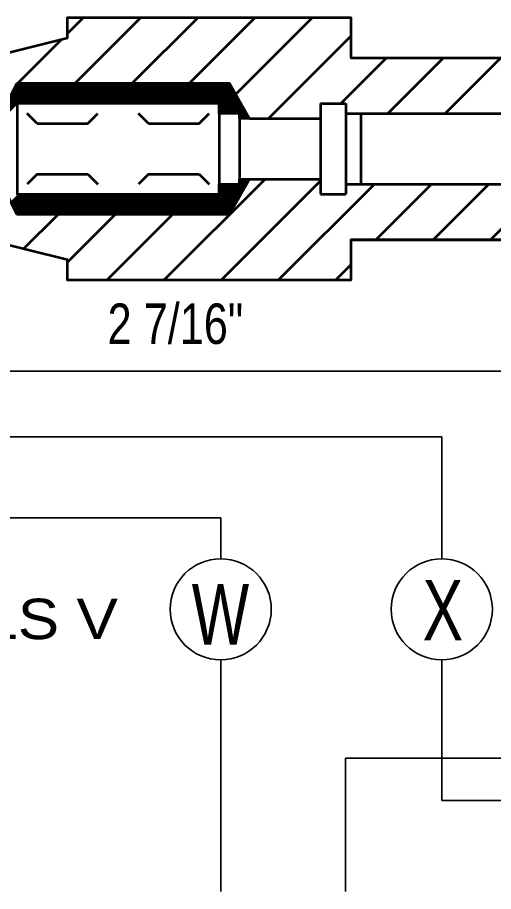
# Model space of a CAD drawing. Extents: x -1 to 679, y 0 to 440.
# Drawn here: x 318.92 to 342.46, y 108.8 to 152.05 of the extents above; entities that cross this region are included whole.
import ezdxf

# ---------------------------------------------------------------- set-up
doc = ezdxf.new("R2010")
doc.units = 0
doc.header["$LTSCALE"] = 0.8
doc.layers.add('1', color=7, linetype='Continuous', lineweight=53)

msp = doc.modelspace()

# ---------------------------------------------------------------- linework, layer by layer
at = {"layer": '1'}
for p, q in [((321.3991, 151.2609), (322.1895, 152.0513)), ((321.7679, 148.8013), (325.0179, 152.0513)), ((324.5963, 148.8013), (327.8463, 152.0513)), ((327.4248, 148.8013), (330.6748, 152.0513)), ((329.7097, 148.2577), (333.5032, 152.0513)), ((318.9395, 148.8013), (321.1197, 150.9815)), ((331.3317, 147.0513), (335.3991, 151.1188)), ((334.9101, 147.8013), (337.1601, 150.0513)), ((337.2385, 147.3013), (339.9885, 150.0513)), ((340.0669, 147.3013), (342.8169, 150.0513)), ((316.5665, 145.9263), (319.4415, 148.8013)), ((316.7079, 145.9263), (319.5829, 148.8013)), ((316.8493, 145.9263), (319.7243, 148.8013)), ((316.9907, 145.9263), (319.8657, 148.8013)), ((318.4981, 147.9994), (319.3001, 148.8013)), ((318.6395, 148.2823), (319.1587, 148.8013)), ((318.7809, 148.5651), (319.0172, 148.8013)), ((319.0072, 147.8013), (320.0072, 148.8013)), ((319.1486, 147.8013), (320.1486, 148.8013)), ((319.29, 147.8013), (320.29, 148.8013)), ((319.4314, 147.8013), (320.4314, 148.8013)), ((319.5728, 147.8013), (320.5728, 148.8013)), ((319.7142, 147.8013), (320.7142, 148.8013)), ((319.8557, 147.8013), (320.8557, 148.8013)), ((319.9971, 147.8013), (320.9971, 148.8013)), ((320.1385, 147.8013), (321.1385, 148.8013)), ((320.2799, 147.8013), (321.2799, 148.8013)), ((320.4214, 147.8013), (321.4214, 148.8013)), ((320.5628, 147.8013), (321.5628, 148.8013)), ((320.7043, 147.8013), (321.7043, 148.8013)), ((320.8457, 147.8013), (321.8457, 148.8013)), ((320.9871, 147.8013), (321.9871, 148.8013)), ((321.1285, 147.8013), (322.1285, 148.8013)), ((321.2699, 147.8013), (322.2699, 148.8013)), ((321.4113, 147.8013), (322.4113, 148.8013)), ((321.5528, 147.8013), (322.5528, 148.8013)), ((321.6942, 147.8013), (322.6942, 148.8013)), ((321.8356, 147.8013), (322.8356, 148.8013)), ((321.977, 147.8013), (322.977, 148.8013)), ((322.1184, 147.8013), (323.1184, 148.8013)), ((322.2598, 147.8013), (323.2598, 148.8013)), ((322.4013, 147.8013), (323.4013, 148.8013)), ((322.5427, 147.8013), (323.5427, 148.8013)), ((322.6841, 147.8013), (323.6841, 148.8013)), ((322.8255, 147.8013), (323.8255, 148.8013)), ((322.967, 147.8013), (323.967, 148.8013)), ((323.1084, 147.8013), (324.1084, 148.8013)), ((323.2498, 147.8013), (324.2498, 148.8013)), ((323.3913, 147.8013), (324.3913, 148.8013)), ((323.5327, 147.8013), (324.5327, 148.8013)), ((323.6741, 147.8013), (324.6741, 148.8013)), ((323.8155, 147.8013), (324.8155, 148.8013)), ((323.9569, 147.8013), (324.9569, 148.8013)), ((324.0983, 147.8013), (325.0983, 148.8013)), ((324.2398, 147.8013), (325.2398, 148.8013)), ((324.3812, 147.8013), (325.3812, 148.8013)), ((324.5226, 147.8013), (325.5226, 148.8013)), ((324.664, 147.8013), (325.664, 148.8013)), ((324.8054, 147.8013), (325.8054, 148.8013)), ((324.9468, 147.8013), (325.9468, 148.8013)), ((325.0883, 147.8013), (326.0883, 148.8013)), ((325.2297, 147.8013), (326.2297, 148.8013)), ((325.3711, 147.8013), (326.3711, 148.8013)), ((325.5126, 147.8013), (326.5126, 148.8013)), ((325.654, 147.8013), (326.654, 148.8013)), ((325.7954, 147.8013), (326.7954, 148.8013)), ((325.9368, 147.8013), (326.9368, 148.8013)), ((326.0782, 147.8013), (327.0782, 148.8013)), ((326.2197, 147.8013), (327.2197, 148.8013)), ((326.3611, 147.8013), (327.3611, 148.8013)), ((326.5025, 147.8013), (327.5025, 148.8013)), ((326.6439, 147.8013), (327.6439, 148.8013)), ((326.7853, 147.8013), (327.7853, 148.8013)), ((326.9267, 147.8013), (327.9267, 148.8013)), ((327.0682, 147.8013), (328.0682, 148.8013)), ((327.2096, 147.8013), (328.2096, 148.8013)), ((327.351, 147.8013), (328.351, 148.8013)), ((327.4924, 147.8013), (328.4924, 148.8013)), ((327.6338, 147.8013), (328.6338, 148.8013)), ((327.7752, 147.8013), (328.7752, 148.8013)), ((327.9167, 147.8013), (328.9167, 148.8013)), ((328.0582, 147.8013), (329.0582, 148.8013)), ((328.1996, 147.8013), (329.1996, 148.8013)), ((328.341, 147.8013), (329.341, 148.8013)), ((328.4824, 147.8013), (329.4294, 148.7483)), ((328.6238, 147.8013), (329.4808, 148.6583)), ((328.7652, 147.8013), (329.5322, 148.5683)), ((328.8991, 147.7937), (329.5837, 148.4783)), ((328.8991, 147.6523), (329.6351, 148.3883)), ((328.8991, 147.5109), (329.6865, 148.2983)), ((328.8991, 147.3695), (329.7379, 148.2083)), ((328.9723, 147.3013), (329.7893, 148.1183)), ((329.1137, 147.3013), (329.8408, 148.0283)), ((329.2552, 147.3013), (329.8922, 147.9383)), ((329.3966, 147.3013), (329.9437, 147.8483)), ((329.538, 147.3013), (329.9951, 147.7583)), ((329.6794, 147.3013), (330.0465, 147.6683)), ((329.8208, 147.3013), (330.0979, 147.5784)), ((329.8991, 147.2381), (330.1493, 147.4884)), ((333.8991, 147.8013), (333.8991, 143.3013)), ((333.8991, 147.8013), (335.1491, 147.8013)), ((335.1491, 147.8013), (335.1491, 143.3013)), ((319.8991, 146.8013), (319.3991, 147.3013)), ((322.3991, 146.8013), (322.8991, 147.3013)), ((325.3991, 146.8013), (324.8991, 147.3013)), ((327.8991, 146.8013), (328.3991, 147.3013)), ((328.8991, 147.3013), (328.8991, 143.8013)), ((329.8991, 147.0967), (330.2007, 147.3984)), ((329.8991, 147.0513), (329.8991, 144.0513)), ((329.9952, 147.0513), (330.2522, 147.3084)), ((330.1366, 147.0513), (330.3036, 147.2184)), ((330.278, 147.0513), (330.3551, 147.1284)), ((330.3991, 147.0513), (333.8991, 147.0513)), ((335.1491, 147.3013), (345.3991, 147.3013)), ((335.8991, 147.3013), (335.8991, 143.8013)), ((319.8991, 146.8013), (322.3991, 146.8013)), ((325.3991, 146.8013), (327.8991, 146.8013)), ((319.8991, 144.3013), (319.3991, 143.8013)), ((319.8991, 144.3013), (322.3991, 144.3013)), ((322.3991, 144.3013), (322.8991, 143.8013)), ((325.3991, 144.3013), (324.8991, 143.8013)), ((325.3991, 144.3013), (327.8991, 144.3013)), ((326.1601, 139.0513), (331.1601, 144.0513)), ((327.8991, 144.3013), (328.3991, 143.8013)), ((328.4978, 142.3013), (330.2478, 144.0513)), ((328.6393, 142.3013), (330.3893, 144.0513)), ((329.8991, 143.9854), (329.965, 144.0513)), ((329.8991, 143.844), (330.1064, 144.0513)), ((330.3991, 144.0513), (333.8991, 144.0513)), ((327.9322, 142.3013), (329.4322, 143.8013)), ((328.0736, 142.3013), (329.5736, 143.8013)), ((328.215, 142.3013), (329.715, 143.8013)), ((328.3564, 142.3013), (329.8564, 143.8013)), ((328.7807, 142.3013), (330.2237, 143.7443)), ((328.8991, 143.6925), (329.0079, 143.8013)), ((328.8991, 143.5511), (329.1493, 143.8013)), ((328.8991, 143.4097), (329.2908, 143.8013)), ((328.9885, 139.0513), (333.8991, 143.9619)), ((331.8169, 139.0513), (336.5669, 143.8013)), ((335.1491, 143.8013), (345.3991, 143.8013)), ((336.6453, 141.0513), (339.3953, 143.8013)), ((339.4738, 141.0513), (342.2238, 143.8013)), ((342.3023, 141.0513), (345.0523, 143.8013)), ((318.6103, 142.8789), (319.0327, 143.3013)), ((318.6574, 142.7847), (319.1741, 143.3013)), ((318.7046, 142.6904), (319.3155, 143.3013)), ((318.7517, 142.5961), (319.4569, 143.3013)), ((318.7988, 142.5018), (319.5983, 143.3013)), ((318.846, 142.4076), (319.7398, 143.3013)), ((318.8931, 142.3132), (319.8812, 143.3013)), ((319.0226, 142.3013), (320.0226, 143.3013)), ((319.164, 142.3013), (320.164, 143.3013)), ((319.3054, 142.3013), (320.3054, 143.3013)), ((319.4468, 142.3013), (320.4468, 143.3013)), ((319.5883, 142.3013), (320.5883, 143.3013)), ((319.7297, 142.3013), (320.7297, 143.3013)), ((319.8711, 142.3013), (320.8711, 143.3013)), ((320.0126, 142.3013), (321.0126, 143.3013)), ((320.154, 142.3013), (321.154, 143.3013)), ((320.2954, 142.3013), (321.2954, 143.3013)), ((320.4368, 142.3013), (321.4368, 143.3013)), ((320.5782, 142.3013), (321.5782, 143.3013)), ((320.7197, 142.3013), (321.7197, 143.3013)), ((320.8611, 142.3013), (321.8611, 143.3013)), ((321.0025, 142.3013), (322.0025, 143.3013)), ((321.1439, 142.3013), (322.1439, 143.3013)), ((321.2853, 142.3013), (322.2853, 143.3013)), ((321.4267, 142.3013), (322.4267, 143.3013)), ((321.5682, 142.3013), (322.5682, 143.3013)), ((321.7096, 142.3013), (322.7096, 143.3013)), ((321.851, 142.3013), (322.851, 143.3013)), ((321.9924, 142.3013), (322.9924, 143.3013)), ((322.1338, 142.3013), (323.1338, 143.3013)), ((322.2752, 142.3013), (323.2752, 143.3013)), ((322.4167, 142.3013), (323.4167, 143.3013)), ((322.5582, 142.3013), (323.5582, 143.3013)), ((322.6996, 142.3013), (323.6996, 143.3013)), ((322.841, 142.3013), (323.841, 143.3013)), ((322.9824, 142.3013), (323.9824, 143.3013)), ((323.1238, 142.3013), (324.1238, 143.3013)), ((323.2652, 142.3013), (324.2652, 143.3013)), ((323.4067, 142.3013), (324.4067, 143.3013)), ((323.5481, 142.3013), (324.5481, 143.3013)), ((323.6895, 142.3013), (324.6895, 143.3013)), ((323.8309, 142.3013), (324.8309, 143.3013)), ((323.9723, 142.3013), (324.9723, 143.3013)), ((324.1137, 142.3013), (325.1137, 143.3013)), ((324.2552, 142.3013), (325.2552, 143.3013)), ((324.3966, 142.3013), (325.3966, 143.3013)), ((324.538, 142.3013), (325.538, 143.3013)), ((324.6794, 142.3013), (325.6794, 143.3013)), ((324.8208, 142.3013), (325.8208, 143.3013)), ((324.9623, 142.3013), (325.9623, 143.3013)), ((325.1037, 142.3013), (326.1037, 143.3013)), ((325.2452, 142.3013), (326.2452, 143.3013)), ((325.3866, 142.3013), (326.3866, 143.3013)), ((325.528, 142.3013), (326.528, 143.3013)), ((325.6694, 142.3013), (326.6694, 143.3013)), ((325.8108, 142.3013), (326.8108, 143.3013)), ((325.9522, 142.3013), (326.9522, 143.3013)), ((326.0937, 142.3013), (327.0937, 143.3013)), ((326.2351, 142.3013), (327.2351, 143.3013)), ((326.3765, 142.3013), (327.3765, 143.3013)), ((326.5179, 142.3013), (327.5179, 143.3013)), ((326.6593, 142.3013), (327.6593, 143.3013)), ((326.8007, 142.3013), (327.8007, 143.3013)), ((326.9422, 142.3013), (327.9422, 143.3013)), ((327.0836, 142.3013), (328.0836, 143.3013)), ((327.225, 142.3013), (328.225, 143.3013)), ((327.3664, 142.3013), (328.3664, 143.3013)), ((327.5079, 142.3013), (328.5079, 143.3013)), ((327.6493, 142.3013), (328.6493, 143.3013)), ((327.7908, 142.3013), (328.7908, 143.3013)), ((328.9221, 142.3013), (330.0351, 143.4143)), ((333.8991, 143.3013), (335.1491, 143.3013)), ((329.0635, 142.3013), (329.8465, 143.0843)), ((329.2049, 142.3013), (329.6579, 142.7543)), ((319.2197, 140.5962), (320.9248, 142.3013)), ((321.3991, 139.9472), (323.7532, 142.3013)), ((323.3317, 139.0513), (326.5817, 142.3013)), ((329.3463, 142.3013), (329.4694, 142.4243)), ((335.3991, 141.0513), (345.3991, 141.0513)), ((334.6453, 139.0513), (335.3991, 139.8051)), ((335.3991, 139.0513), (321.3991, 139.0513))]:
    msp.add_line(p, q, dxfattribs=at)
at = {"layer": '1', "lineweight": 35}
for p, q in [((306.3991, 134.5513), (345.3991, 134.5513)), ((286.3991, 131.3013), (339.8991, 131.3013)), ((339.8991, 131.3013), (339.8991, 125.2666)), ((298.8991, 127.2931), (328.9684, 127.2931)), ((328.9684, 127.2933), (328.9684, 127.2931)), ((328.9684, 127.2931), (328.9684, 125.2667)), ((328.9684, 120.2667), (328.9684, 108.8013)), ((339.8991, 120.2666), (339.8991, 113.3013)), ((335.1377, 115.4007), (335.1377, 108.8013)), ((349.3991, 115.4007), (335.1377, 115.4007)), ((335.1377, 115.4007), (335.1377, 110.9007)), ((339.8991, 113.3013), (386.3738, 113.3013))]:
    msp.add_line(p, q, dxfattribs=at)
at = {"layer": '1'}
for points in [[(315.3991, 149.5513), (321.3991, 151.0513), (321.3991, 152.0513), (335.3991, 152.0513), (335.3991, 150.0513), (345.3991, 150.0513), (345.3991, 143.8013), (345.3991, 141.0513), (335.3991, 141.0513), (335.3991, 139.0513), (321.3991, 139.0513), (321.3991, 140.0513), (315.3991, 141.5513), (306.3991, 141.5513), (306.3991, 143.3013)], [(298.8991, 147.8013), (318.3991, 147.8013), (318.8991, 148.8013), (329.3991, 148.8013), (330.3991, 147.0513), (329.8991, 147.0513), (329.8991, 147.3013), (328.8991, 147.3013), (328.8991, 147.8013), (318.8991, 147.8013), (318.8991, 143.3013), (328.8991, 143.3013), (328.8991, 143.8013), (329.8991, 143.8013), (329.8991, 144.0513), (330.3991, 144.0513), (329.3991, 142.3013), (318.8991, 142.3013), (318.3991, 143.3013), (293.8991, 143.3013)]]:
    msp.add_lwpolyline(points, dxfattribs=at)
msp.add_lwpolyline([(293.8991, 143.3013), (293.8991, 147.8013), (318.3991, 147.8013), (318.8991, 148.8013), (329.3991, 148.8013), (330.3991, 147.0513), (329.8991, 147.0513), (329.8991, 147.3013), (328.8991, 147.3013), (328.8991, 147.8013), (318.8991, 147.8013), (318.8991, 143.3013), (328.8991, 143.3013), (328.8991, 143.8013), (329.8991, 143.8013), (329.8991, 144.0513), (330.3991, 144.0513), (329.3991, 142.3013), (318.8991, 142.3013), (318.3991, 143.3013)], close=True, dxfattribs=at)
msp.add_lwpolyline([(293.8991, 143.3013), (293.8991, 147.8013), (318.3991, 147.8013), (318.8991, 148.8013), (329.3991, 148.8013), (330.3991, 147.0513), (329.8991, 147.0513), (329.8991, 147.3013), (328.8991, 147.3013), (328.8991, 147.8013), (318.8991, 147.8013), (318.8991, 143.3013), (328.8991, 143.3013), (328.8991, 143.8013), (329.8991, 143.8013), (329.8991, 144.0513), (330.3991, 144.0513), (329.3991, 142.3013), (318.8991, 142.3013), (318.3991, 143.3013)], close=True, dxfattribs=at)
at = {"layer": '1', "lineweight": 35}
for centre in [(328.9684, 122.7667), (339.8991, 122.7666)]:
    msp.add_circle(centre, 2.5, dxfattribs=at)

# ---------------------------------------------------------------- texts
at = {"layer": '1'}
for s, height, width, p in [('2 7/16"', 2, 0.8, (323.3727, 135.8988)), ('X', 3, 0.75, (338.9497, 121.2233)), ('W', 3, 0.75, (327.5353, 121.0226)), ('IDENTIFYING SYMBOLS V', 2, 1.15, (285.7758, 121.2906))]:
    msp.add_text(s, height=height, dxfattribs=dict(at, width=width)).set_placement(p)

doc.saveas('drawing.dxf')
